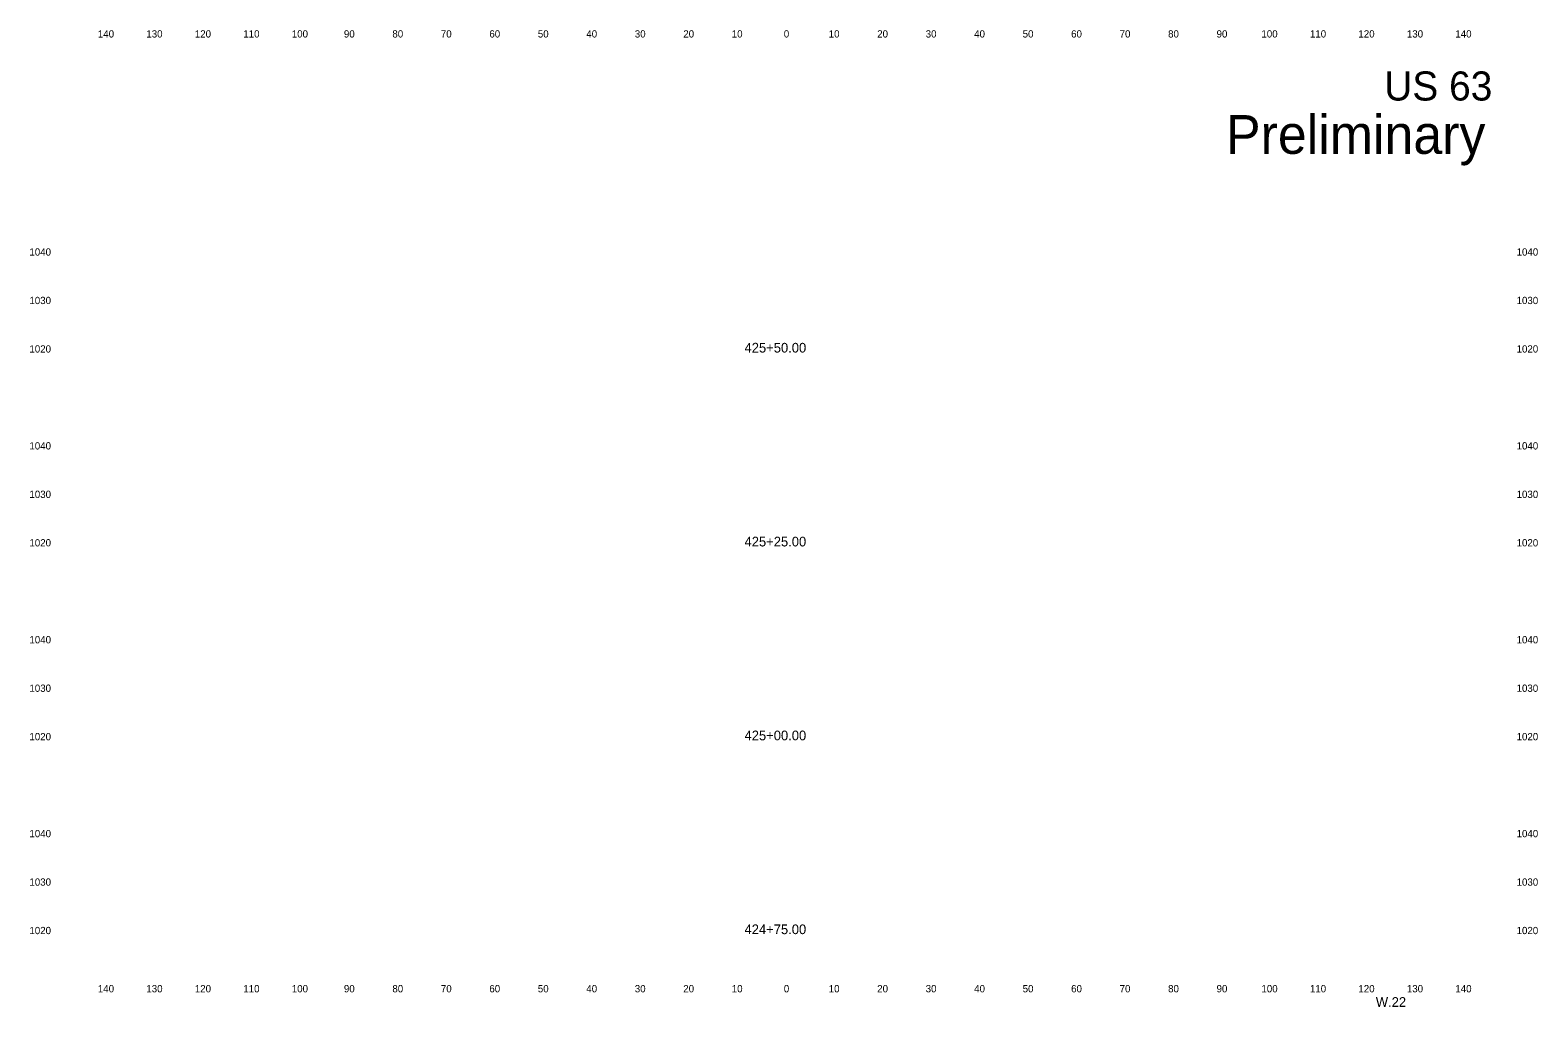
# Model space of a CAD drawing. Extents: x 10123 to 17295, y 9730 to 10181.
# Drawn here: x 10133.3 to 10444.3, y 9979 to 10180.5 of the extents above; entities that cross this region are included whole.
import ezdxf

# ---------------------------------------------------------------- set-up
doc = ezdxf.new("R2010")
doc.units = 0
for name, color, linetype in [('dsnTextCpn', 7, 'Continuous'), ('dsnTextCpnTitleSheetLocDesc', 7, 'Continuous'), ('dsnTextCpnTitleSheetPIN', 7, 'Continuous')]:
    doc.layers.add(name, color=color, linetype=linetype)

msp = doc.modelspace()

# ---------------------------------------------------------------- texts
at = {"layer": 'dsnTextCpn'}
for s, height, p in [('140', 1.5, (10147.27, 10179)), ('130', 1.5, (10157.27, 10179)), ('120', 1.5, (10167.27, 10179)), ('110', 1.5, (10177.27, 10179)), ('100', 1.5, (10187.27, 10179)), ('90', 1.5, (10198.02, 10179)), ('80', 1.5, (10208.02, 10179)), ('70', 1.5, (10218.02, 10179)), ('60', 1.5, (10228.02, 10179)), ('50', 1.5, (10238.02, 10179)), ('40', 1.5, (10248.02, 10179)), ('30', 1.5, (10258.02, 10179)), ('20', 1.5, (10268.02, 10179)), ('10', 1.5, (10278.02, 10179)), ('0', 1.5, (10288.76, 10179)), ('0', 1.5, (10288.76, 10179)), ('10', 1.5, (10298.02, 10179)), ('20', 1.5, (10308.02, 10179)), ('30', 1.5, (10318.02, 10179)), ('40', 1.5, (10328.02, 10179)), ('50', 1.5, (10338.02, 10179)), ('60', 1.5, (10348.02, 10179)), ('70', 1.5, (10358.02, 10179)), ('80', 1.5, (10368.02, 10179)), ('90', 1.5, (10378.02, 10179)), ('100', 1.5, (10387.27, 10179)), ('110', 1.5, (10397.27, 10179)), ('120', 1.5, (10407.27, 10179)), ('130', 1.5, (10417.27, 10179)), ('140', 1.5, (10427.27, 10179)), ('US 63', 6, (10412.6, 10166)), ('1040', 1.5, (10133.15, 10134)), ('1040', 1.5, (10439.9, 10134)), ('1030', 1.5, (10133.15, 10124)), ('1030', 1.5, (10439.9, 10124)), ('1020', 1.5, (10133.15, 10114)), ('425+50.00', 2, (10280.66, 10114)), ('1020', 1.5, (10439.9, 10114)), ('1040', 1.5, (10133.15, 10094)), ('1040', 1.5, (10439.9, 10094)), ('1030', 1.5, (10133.15, 10084)), ('1030', 1.5, (10439.9, 10084)), ('425+25.00', 2, (10280.66, 10074)), ('1020', 1.5, (10133.15, 10074)), ('1020', 1.5, (10439.9, 10074)), ('1040', 1.5, (10133.15, 10054)), ('1040', 1.5, (10439.9, 10054)), ('1030', 1.5, (10133.15, 10044)), ('1030', 1.5, (10439.9, 10044)), ('1020', 1.5, (10133.15, 10034)), ('425+00.00', 2, (10280.66, 10034)), ('1020', 1.5, (10439.9, 10034)), ('1040', 1.5, (10133.15, 10014)), ('1040', 1.5, (10439.9, 10014)), ('1030', 1.5, (10133.15, 10004)), ('1030', 1.5, (10439.9, 10004)), ('1020', 1.5, (10133.15, 9994)), ('424+75.00', 2, (10280.66, 9994)), ('1020', 1.5, (10439.9, 9994)), ('140', 1.5, (10147.27, 9982)), ('130', 1.5, (10157.27, 9982)), ('120', 1.5, (10167.27, 9982)), ('110', 1.5, (10177.27, 9982)), ('100', 1.5, (10187.27, 9982)), ('90', 1.5, (10198.02, 9982)), ('80', 1.5, (10208.02, 9982)), ('70', 1.5, (10218.02, 9982)), ('60', 1.5, (10228.02, 9982)), ('50', 1.5, (10238.02, 9982)), ('40', 1.5, (10248.02, 9982)), ('30', 1.5, (10258.02, 9982)), ('20', 1.5, (10268.02, 9982)), ('10', 1.5, (10278.02, 9982)), ('0', 1.5, (10288.76, 9982)), ('0', 1.5, (10288.76, 9982)), ('10', 1.5, (10298.02, 9982)), ('20', 1.5, (10308.02, 9982)), ('30', 1.5, (10318.02, 9982)), ('40', 1.5, (10328.02, 9982)), ('50', 1.5, (10338.02, 9982)), ('60', 1.5, (10348.02, 9982)), ('70', 1.5, (10358.02, 9982)), ('80', 1.5, (10368.02, 9982)), ('90', 1.5, (10378.02, 9982)), ('100', 1.5, (10387.27, 9982)), ('110', 1.5, (10397.27, 9982)), ('120', 1.5, (10407.27, 9982)), ('130', 1.5, (10417.27, 9982)), ('140', 1.5, (10427.27, 9982))]:
    msp.add_text(s, height=height, dxfattribs=at).set_placement(p)
at = {"layer": 'dsnTextCpnTitleSheetLocDesc'}
msp.add_text('Preliminary', height=8, dxfattribs=at).set_placement((10379.97, 10155))
at = {"layer": 'dsnTextCpnTitleSheetPIN'}
msp.add_text('W.22', height=2, dxfattribs=at).set_placement((10410.87, 9979))

doc.saveas('drawing.dxf')
